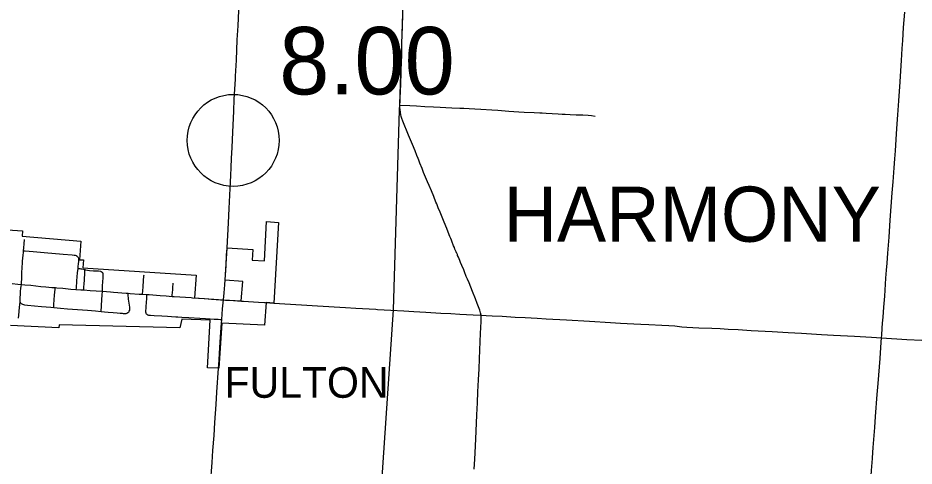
# Model space of a CAD drawing. Extents: x 1813937 to 1948437, y 826606 to 1022856.
# Drawn here: x 1875578 to 1890191, y 894473 to 901785 of the extents above; entities that cross this region are included whole.
import ezdxf

# ---------------------------------------------------------------- set-up
doc = ezdxf.new("R2010")
doc.units = 0
for name, color, linetype in [('Default', 7, 'Continuous'), ('GM_X_City_Street', 7, 'Continuous'), ('GM_X_Corporation', 7, 'Continuous'), ('GM_X_Corporation_Text', 7, 'Continuous'), ('GM_X_County_Road', 7, 'Continuous'), ('GM_X_State_Route', 7, 'Continuous'), ('GM_X_Township', 7, 'Continuous'), ('GM_X_Township_Road', 7, 'Continuous'), ('GM_X_Township_Text', 7, 'Continuous')]:
    doc.layers.add(name, color=color, linetype=linetype)

msp = doc.modelspace()

# ---------------------------------------------------------------- linework, layer by layer
at = {"layer": 'Default'}
msp.add_circle((1879089, 899787), 750, dxfattribs=at)
at = {"layer": 'GM_X_City_Street'}
for points in [[(1875671, 897987), (1875675, 898035), (1875681, 898097), (1875688, 898169)], [(1875637, 897437), (1875638, 897457), (1875641, 897538), (1875642, 897571), (1875644, 897620), (1875648, 897718), (1875651, 897784), (1875654, 897817), (1875659, 897865), (1875665, 897913), (1875669, 897960), (1875671, 897987)], [(1875671, 897987), (1875696, 897985), (1875826, 897975), (1876005, 897958), (1876315, 897931), (1876462, 897919), (1876494, 897915), (1876510, 897912), (1876526, 897907), (1876541, 897900), (1876546, 897896), (1876551, 897891)], [(1876568, 897837), (1876568, 897823), (1876566, 897807), (1876562, 897778), (1876557, 897726), (1876554, 897695)], [(1876554, 897695), (1876547, 897626), (1876535, 897494), (1876526, 897378), (1876524, 897355)], [(1876554, 897695), (1876568, 897695), (1876587, 897695), (1876603, 897693), (1876619, 897689), (1876669, 897678)], [(1876652, 897346), (1876654, 897370), (1876655, 897386), (1876660, 897453), (1876664, 897503), (1876668, 897635), (1876669, 897666), (1876669, 897678)], [(1876669, 897678), (1876682, 897675), (1876714, 897669), (1876746, 897665), (1876810, 897660), (1876891, 897657), (1876923, 897654), (1876938, 897650), (1876954, 897638)], [(1876955, 897326), (1876957, 897415), (1876967, 897545), (1876969, 897593), (1876968, 897609), (1876964, 897625), (1876954, 897638)], [(1877611, 897277), (1877611, 897292), (1877613, 897318), (1877619, 897416), (1877624, 897482), (1877626, 897515), (1877631, 897554), (1877634, 897579), (1877637, 897594)], [(1875487, 897451), (1875579, 897442), (1875637, 897437)], [(1875615, 897147), (1875614, 897176), (1875621, 897323), (1875626, 897373), (1875631, 897405), (1875637, 897437)], [(1875637, 897437), (1875692, 897432), (1875789, 897422), (1875953, 897404), (1876035, 897397), (1876133, 897389), (1876190, 897384)], [(1876163, 897059), (1876164, 897078), (1876165, 897111), (1876170, 897184), (1876177, 897263), (1876188, 897358), (1876190, 897384)], [(1876190, 897384), (1876214, 897382), (1876312, 897373), (1876443, 897361), (1876524, 897355)], [(1878095, 897241), (1878096, 897259), (1878102, 897346), (1878106, 897395), (1878111, 897442), (1878112, 897457)], [(1876524, 897355), (1876606, 897349), (1876652, 897346)], [(1876652, 897346), (1876754, 897339), (1876852, 897331), (1876955, 897326)], [(1876934, 896997), (1876940, 897089), (1876948, 897193), (1876953, 897262), (1876955, 897326)], [(1876955, 897326), (1877086, 897315), (1877138, 897311), (1877344, 897295), (1877378, 897293)], [(1877385, 896989), (1877395, 897001), (1877402, 897016), (1877405, 897032), (1877405, 897049), (1877404, 897065), (1877400, 897098), (1877383, 897196), (1877379, 897225), (1877377, 897246), (1877377, 897279), (1877378, 897293)], [(1877378, 897293), (1877408, 897290), (1877554, 897280), (1877611, 897277)], [(1877611, 897277), (1877682, 897272)], [(1877686, 896947), (1877677, 896954), (1877671, 896963), (1877667, 896971), (1877665, 896978), (1877663, 896994), (1877663, 897011), (1877667, 897043), (1877671, 897092), (1877673, 897125), (1877675, 897158), (1877678, 897191), (1877681, 897250), (1877682, 897272)], [(1877682, 897272), (1877717, 897270), (1877897, 897256), (1877995, 897248), (1878095, 897241)], [(1878095, 897241), (1878126, 897239), (1878405, 897221), (1878425, 897220)], [(1875588, 896886), (1875594, 896935), (1875605, 897059), (1875610, 897108), (1875615, 897147)], [(1875615, 897147), (1875621, 897138), (1875627, 897130), (1875634, 897125), (1875643, 897120), (1875655, 897113), (1875670, 897108), (1875686, 897105), (1875735, 897098), (1875849, 897088), (1875963, 897078), (1876114, 897063), (1876163, 897059)], [(1879223, 897165), (1879255, 897163), (1879499, 897148), (1879597, 897141), (1879613, 897141)], [(1876163, 897059), (1876273, 897049), (1876387, 897041), (1876550, 897028), (1876713, 897015), (1876844, 897004), (1876934, 896997)], [(1876934, 896997), (1876992, 896991), (1877049, 896986), (1877131, 896980), (1877197, 896973), (1877246, 896968), (1877278, 896965), (1877294, 896963), (1877310, 896963), (1877326, 896963), (1877341, 896964), (1877355, 896969), (1877369, 896976), (1877385, 896989)], [(1877686, 896947), (1877693, 896943), (1877699, 896940), (1877707, 896937), (1877715, 896936), (1877740, 896934), (1877801, 896931), (1877924, 896922), (1878018, 896916), (1878082, 896912), (1878154, 896909), (1878184, 896907), (1878249, 896904), (1878363, 896898), (1878542, 896888), (1878636, 896881), (1878711, 896876), (1878779, 896872), (1878845, 896868), (1878877, 896867), (1878902, 896866)]]:
    msp.add_lwpolyline(points, dxfattribs=at)
at = {"layer": 'GM_X_Corporation'}
msp.add_lwpolyline([(1875079, 898348), (1875653, 898309), (1875647, 898225), (1876603, 898141), (1876581, 897839), (1876646, 897838), (1876637, 897710), (1878484, 897585), (1878460, 897219), (1878613, 897206), (1878930, 897186), (1879221, 897171), (1879244, 897487), (1878959, 897508), (1878990, 898034), (1879410, 898009), (1879398, 897835), (1879597, 897822), (1879630, 898461), (1879830, 898445), (1879753, 897133), (1879629, 897141), (1879598, 896771), (1878904, 896804), (1878854, 896070), (1878672, 896076), (1878714, 896851), (1878252, 896869), (1878219, 896726), (1876250, 896779), (1876247, 896726), (1875458, 896768)], dxfattribs=at)
at = {"layer": 'GM_X_County_Road'}
for points in [[(1889661, 896565), (1889664, 896607), (1889672, 896721), (1889679, 896803), (1889685, 896901), (1889691, 896983), (1889697, 897064), (1889712, 897244), (1889726, 897440), (1889733, 897539), (1889742, 897669), (1889751, 897784), (1889764, 897947), (1889783, 898209), (1889802, 898487), (1889835, 898929), (1889849, 899109), (1889867, 899338), (1889877, 899485), (1889886, 899616), (1889904, 899894), (1889915, 900057), (1889926, 900204), (1889942, 900433), (1889963, 900744), (1889975, 900924), (1889984, 901088), (1889997, 901284), (1890006, 901415), (1890021, 901627), (1890040, 901877)], [(1878425, 897220), (1878620, 897206), (1878734, 897197), (1878881, 897186), (1878928, 897183)], [(1878928, 897183), (1878962, 897181), (1879092, 897174), (1879223, 897165)], [(1879613, 897141), (1879754, 897132)], [(1879754, 897132), (1880202, 897104), (1880464, 897088), (1880922, 897061), (1881086, 897051), (1881413, 897031), (1881441, 897030)], [(1881441, 897030), (1881659, 897019), (1881871, 897004), (1882034, 896996), (1882230, 896984), (1882476, 896970), (1882640, 896962), (1882787, 896953), (1883000, 896941), (1883134, 896934)], [(1883020, 894422), (1883028, 894586), (1883038, 894799), (1883051, 895045), (1883063, 895307), (1883072, 895504), (1883080, 895684), (1883088, 895881), (1883097, 896061), (1883105, 896225), (1883118, 896504), (1883124, 896635), (1883132, 896832), (1883134, 896897), (1883134, 896934)], [(1883134, 896934), (1883213, 896930), (1883311, 896926), (1883475, 896917), (1883687, 896905), (1883851, 896895), (1884047, 896884), (1884194, 896876), (1884522, 896858), (1884899, 896839), (1885243, 896818), (1885406, 896807), (1885619, 896795), (1885734, 896788), (1885864, 896781), (1886078, 896774), (1886192, 896768), (1886291, 896760), (1886405, 896747), (1886486, 896739), (1886584, 896732), (1886682, 896728), (1886896, 896722), (1887027, 896716), (1887158, 896709), (1887321, 896699), (1887534, 896687), (1887878, 896667), (1888140, 896652), (1888353, 896640), (1888517, 896632), (1888681, 896622), (1888877, 896611), (1888992, 896604), (1889221, 896591), (1889499, 896575), (1889661, 896565)], [(1889515, 894607), (1889527, 894775), (1889552, 895102), (1889565, 895282), (1889592, 895642), (1889606, 895822), (1889636, 896230), (1889655, 896492), (1889661, 896565)], [(1889661, 896565), (1890072, 896540), (1890318, 896526), (1890580, 896510), (1890891, 896490), (1891055, 896481), (1891431, 896457), (1891677, 896442), (1891759, 896438)], [(1889363, 892553), (1889369, 892649), (1889379, 892780), (1889393, 892976), (1889407, 893172), (1889419, 893319), (1889431, 893483), (1889432, 893498), (1889441, 893615), (1889443, 893646), (1889456, 893826), (1889474, 894072), (1889499, 894399), (1889514, 894595), (1889515, 894607)]]:
    msp.add_lwpolyline(points, dxfattribs=at)
at = {"layer": 'GM_X_State_Route'}
for points in [[(1878988, 898033), (1879010, 898444), (1879024, 898673), (1879042, 899001), (1879050, 899214), (1879055, 899345), (1879062, 899493), (1879072, 899673), (1879083, 899919), (1879099, 900263), (1879107, 900460), (1879124, 900787), (1879127, 900836), (1879141, 901098), (1879156, 901426), (1879168, 901655), (1879188, 902032), (1879203, 902327), (1879220, 902671), (1879245, 903138)], [(1878982, 897927), (1878985, 897969), (1878988, 898033)], [(1878959, 897509), (1878964, 897593), (1878972, 897740), (1878982, 897927)], [(1878928, 897183), (1878941, 897298), (1878953, 897429), (1878959, 897509)], [(1878897, 896806), (1878901, 896859), (1878902, 896866), (1878914, 897039), (1878928, 897183)], [(1878849, 896071), (1878852, 896118), (1878877, 896492), (1878887, 896655), (1878897, 896806)], [(1878720, 894172), (1878746, 894531), (1878759, 894728), (1878778, 894973), (1878791, 895186), (1878810, 895480), (1878822, 895676), (1878849, 896071)]]:
    msp.add_lwpolyline(points, dxfattribs=at)
at = {"layer": 'GM_X_Township'}
msp.add_lwpolyline([(1880714, 883463), (1880836, 885744), (1880863, 886256), (1881338, 891636), (1881703, 897023), (1881803, 900282), (1881806, 900375), (1881918, 903829), (1881985, 905459), (1882074, 908232), (1882082, 908847), (1882260, 912507), (1887758, 913255), (1888309, 913332)], dxfattribs=at)
at = {"layer": 'GM_X_Township_Road'}
for points in [[(1881808, 900360), (1881809, 900428), (1881813, 900494), (1881817, 900576), (1881823, 900723), (1881827, 900871), (1881828, 900920), (1881833, 901068), (1881836, 901164), (1881837, 901243), (1881837, 901259), (1881838, 901309), (1881840, 901374), (1881844, 901505), (1881848, 901653), (1881856, 901833)], [(1883134, 896934), (1883123, 896973), (1883108, 897017), (1883068, 897125), (1883038, 897202), (1882989, 897323), (1882934, 897460), (1882909, 897520), (1882890, 897565), (1882860, 897641), (1882848, 897672), (1882816, 897747), (1882796, 897794), (1882784, 897825), (1882760, 897883), (1882749, 897910), (1882744, 897923), (1882739, 897934), (1882736, 897943), (1882724, 897970), (1882715, 897991), (1882705, 898014), (1882695, 898040), (1882683, 898067), (1882677, 898082), (1882672, 898097), (1882666, 898112), (1882660, 898127), (1882648, 898157), (1882636, 898188), (1882624, 898218), (1882612, 898248), (1882571, 898351), (1882529, 898454), (1882462, 898615), (1882432, 898689), (1882420, 898719), (1882407, 898749), (1882395, 898779), (1882358, 898870), (1882320, 898961), (1882282, 899052), (1882257, 899112), (1882194, 899265), (1882170, 899326), (1882134, 899417), (1882116, 899462), (1882104, 899492), (1882085, 899538), (1882055, 899614), (1882013, 899721), (1881950, 899872), (1881855, 900099), (1881837, 900145), (1881828, 900177), (1881820, 900209), (1881815, 900241), (1881809, 900290), (1881808, 900322), (1881808, 900360)], [(1881808, 900360), (1881967, 900355), (1882079, 900348), (1882216, 900342), (1882357, 900335), (1882461, 900330), (1882555, 900324), (1882653, 900320), (1882784, 900315), (1882850, 900313), (1882938, 900307), (1883029, 900302), (1883125, 900298), (1883307, 900284), (1883405, 900279), (1883585, 900265), (1883749, 900250), (1883831, 900246), (1883995, 900241), (1884089, 900237), (1884126, 900235), (1884191, 900233), (1884388, 900218), (1884453, 900214), (1884502, 900214), (1884584, 900210), (1884679, 900205), (1884788, 900202), (1884878, 900196), (1884932, 900192), (1884991, 900182)], [(1876551, 897891), (1876557, 897884), (1876563, 897876), (1876566, 897868), (1876568, 897856), (1876568, 897839), (1876568, 897837)]]:
    msp.add_lwpolyline(points, dxfattribs=at)

# ---------------------------------------------------------------- texts
at = {"layer": 'Default'}
msp.add_text('8.00', height=1100, dxfattribs=at).set_placement((1879839, 900537))
at = {"layer": 'GM_X_Corporation_Text'}
msp.add_text('FULTON', height=500, rotation=0, dxfattribs=at).set_placement((1878947, 895587))
at = {"layer": 'GM_X_Township_Text'}
msp.add_text('HARMONY', height=900, rotation=0, dxfattribs=at).set_placement((1883499, 898133))

doc.saveas('drawing.dxf')
